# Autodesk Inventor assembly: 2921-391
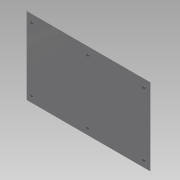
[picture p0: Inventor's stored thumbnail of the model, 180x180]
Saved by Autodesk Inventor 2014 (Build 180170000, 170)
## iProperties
Company: NHTSA/VRTC
Created: 2012-02
Part Number: 2921-391
Project: CHILD SIDE IMPACT SLED
Description: SEAT BACK CUSHION MTG. PLATE ASS'Y.
Document SubType Name: Assembly
Designer: Mike Vanvoorhis
Mass: 1949.62 g
Surface Area: 7084.17 cm^2
Volume: 713.514 cm^3
Density: 2.73242 g/cm^3
Title: Seat Back Cushion Mtg. Plate Ass'y.
Subject: Child Side Impact Sled
Author: Dave Walker
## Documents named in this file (3)
- B:\VRTC_DWG\BIO\Non-P572\Child Side-Frontal Impact Sled\Side Impact Sled\Seat_Back_Cushion_Mounting_Plate_Assembly.iam
- B:\VRTC_DWG\BIO\Non-P572\Child Side-Frontal Impact Sled\Side Impact Sled\Seat_Back_Cushion_Mounting_Plate.ipt
- B:\VRTC_DWG\Inventor Support Files\Content Center\en-US\ANSI ASME B18.2.1(2)\ANSI_ASME B18.2.1 - 1_4-28 UNF - 0.875(2).ipt
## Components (7 placed, 2 different names)
1. 2921-234-1:1 — Insert:1, Insert:2, Insert:3, Insert:4, Insert:5, Insert:6
2. Hex Bolt - Inch 1/4-28 UNF - 0.875:1 — Insert:1
3. Hex Bolt - Inch 1/4-28 UNF - 0.875:2 — Insert:2
4. Hex Bolt - Inch 1/4-28 UNF - 0.875:3 — Insert:3
5. Hex Bolt - Inch 1/4-28 UNF - 0.875:4 — Insert:4
6. Hex Bolt - Inch 1/4-28 UNF - 0.875:5 — Insert:5
7. Hex Bolt - Inch 1/4-28 UNF - 0.875:6 — Insert:6
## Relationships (6: Insert 6)
- Insert:1: 2921-234-1:1 ↔ Hex Bolt - Inch 1/4-28 UNF - 0.875:1
- Insert:2: 2921-234-1:1 ↔ Hex Bolt - Inch 1/4-28 UNF - 0.875:2
- Insert:3: 2921-234-1:1 ↔ Hex Bolt - Inch 1/4-28 UNF - 0.875:3
- Insert:4: 2921-234-1:1 ↔ Hex Bolt - Inch 1/4-28 UNF - 0.875:4
- Insert:5: 2921-234-1:1 ↔ Hex Bolt - Inch 1/4-28 UNF - 0.875:5
- Insert:6: 2921-234-1:1 ↔ Hex Bolt - Inch 1/4-28 UNF - 0.875:6
